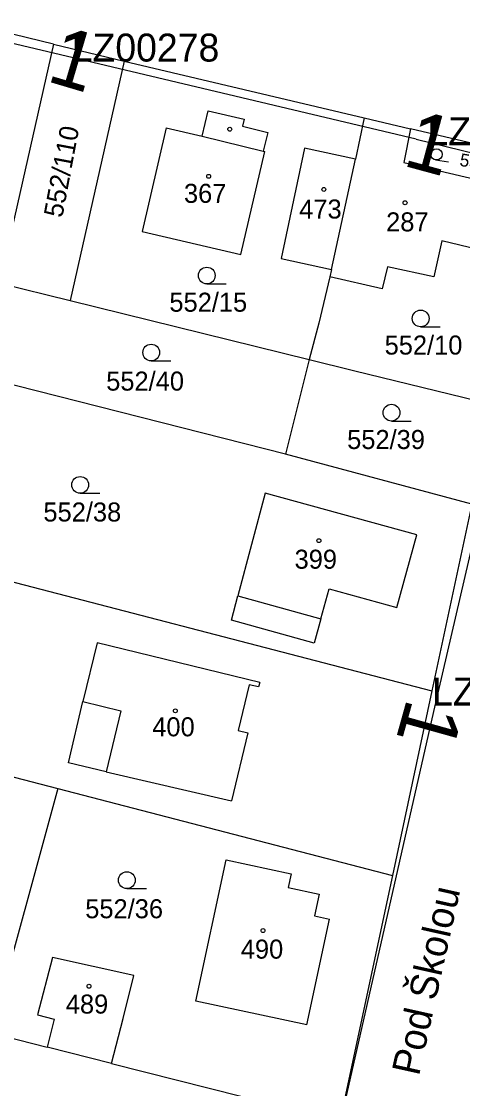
# Model space of a CAD drawing. Extents: x -738131 to -734179, y -1033447 to -1030078.
# Drawn here: x -735741.5 to -735702.1, y -1032052.3 to -1031956.9 of the extents above; entities that cross this region are included whole.
import ezdxf

# ---------------------------------------------------------------- set-up
doc = ezdxf.new("R2010")
doc.units = 0
for name, color, linetype in [('ftf_2010', 7, 'Continuous'), ('ftf_3010', 7, 'Continuous'), ('ftf_3010_ftf_3010_gtda_3015_gtda_3015_1', 7, 'Continuous'), ('ftf_nu', 7, 'Continuous'), ('Vrstva 1', 7, 'Continuous'), ('Vrstva 2', 7, 'Continuous'), ('Vrstva 3', 7, 'Continuous'), ('Vrstva 4', 7, 'Continuous'), ('Vrstva 5', 7, 'Continuous')]:
    doc.layers.add(name, color=color, linetype=linetype)

msp = doc.modelspace()

# ---------------------------------------------------------------- linework, layer by layer
at = {"layer": 'ftf_2010'}
for points in [[(-735738.005, -1031959.865), (-735766.976, -1031952.978)], [(-735706.213, -1031967.386), (-735738.005, -1031959.865)], [(-735706.213, -1031967.386), (-735694.255, -1031970.331), (-735693.952, -1031970.457), (-735694.586, -1031973.112), (-735694.474, -1031973.737)], [(-735698.776, -1031993.123), (-735704.656, -1032018.561)], [(-735704.656, -1032018.561), (-735713.631, -1032058.021)]]:
    msp.add_lwpolyline(points, dxfattribs=at)
at = {"layer": 'Vrstva 1'}
for points in [[(-735738.64, -1031958.92), (-735780.7, -1031948.62)], [(-735738.64, -1031958.92), (-735742.81, -1031977.4)], [(-735738.64, -1031958.92), (-735732.3, -1031960.42)], [(-735732.3, -1031960.42), (-735737.14, -1031981.83)], [(-735732.3, -1031960.42), (-735710.85, -1031965.49)], [(-735725.35, -1031967.12), (-735724.81, -1031964.85)], [(-735724.81, -1031964.85), (-735721.59, -1031965.61)], [(-735710.85, -1031965.49), (-735711.65, -1031969.18)], [(-735710.85, -1031965.49), (-735706.72, -1031966.47)], [(-735728.55, -1031966.37), (-735730.71, -1031975.65)], [(-735728.55, -1031966.37), (-735725.35, -1031967.12)], [(-735721.59, -1031965.61), (-735721.74, -1031966.25)], [(-735721.74, -1031966.25), (-735719.48, -1031966.79)], [(-735706.72, -1031966.47), (-735707.33, -1031969.47)], [(-735694.82, -1031969.28), (-735706.72, -1031966.47)], [(-735719.48, -1031966.79), (-735719.88, -1031968.46)], [(-735716.19, -1031968.2), (-735718.27, -1031978.06)], [(-735711.65, -1031969.18), (-735716.19, -1031968.2)], [(-735721.88, -1031977.71), (-735719.73, -1031968.49)], [(-735719.88, -1031968.46), (-735719.73, -1031968.49)], [(-735713.78, -1031979.04), (-735711.65, -1031969.18)], [(-735707.33, -1031969.47), (-735695.46, -1031972.26)], [(-735730.71, -1031975.65), (-735721.88, -1031977.71)], [(-735703.92, -1031976.49), (-735704.64, -1031979.7)], [(-735696.73, -1031978.21), (-735703.92, -1031976.49)], [(-735718.27, -1031978.06), (-735713.78, -1031979.04)], [(-735708.78, -1031978.81), (-735709.24, -1031980.76)], [(-735704.64, -1031979.7), (-735708.78, -1031978.81)], [(-735713.92, -1031979.69), (-735714.92, -1031983.85)], [(-735713.78, -1031979.04), (-735713.92, -1031979.69)], [(-735709.24, -1031980.76), (-735713.92, -1031979.69)], [(-735743.46, -1031980.28), (-735737.14, -1031981.83)], [(-735737.14, -1031981.83), (-735715.77, -1031987.08)], [(-735714.92, -1031983.85), (-735715.77, -1031987.08)], [(-735715.77, -1031987.08), (-735717.89, -1031995.55)], [(-735715.77, -1031987.08), (-735711.8, -1031988.06)], [(-735711.8, -1031988.06), (-735699.49, -1031991.09)], [(-735717.89, -1031995.55), (-735745.71, -1031988.48)], [(-735701.23, -1032000.01), (-735717.89, -1031995.55)], [(-735719.7, -1031999.03), (-735722.15, -1032008.2)], [(-735706.14, -1032002.77), (-735719.7, -1031999.03)], [(-735701.23, -1032000.01), (-735704.81, -1032016.7)], [(-735707.93, -1032009.27), (-735706.14, -1032002.77)], [(-735750.22, -1032004.92), (-735704.81, -1032016.7)], [(-735722.73, -1032010.38), (-735722.15, -1032008.2)], [(-735714.73, -1032010.26), (-735714, -1032007.6)], [(-735714, -1032007.6), (-735707.93, -1032009.27)], [(-735714.73, -1032010.26), (-735715.33, -1032012.44)], [(-735715.33, -1032012.44), (-735722.73, -1032010.38)], [(-735734.72, -1032012.42), (-735736, -1032017.67)], [(-735720.2, -1032015.95), (-735734.72, -1032012.42)], [(-735720.2, -1032015.95), (-735720.3, -1032016.36)], [(-735721.15, -1032016.16), (-735722.12, -1032020.25)], [(-735720.3, -1032016.36), (-735721.15, -1032016.16)], [(-735704.81, -1032016.7), (-735708.34, -1032033.2)], [(-735737.3, -1032023.15), (-735736, -1032017.67)], [(-735721.26, -1032020.45), (-735722.71, -1032026.55)], [(-735722.12, -1032020.25), (-735721.26, -1032020.45)], [(-735754.68, -1032021.16), (-735738.23, -1032025.43)], [(-735733.92, -1032023.94), (-735737.3, -1032023.15)], [(-735733.92, -1032023.94), (-735722.71, -1032026.55)], [(-735738.23, -1032025.43), (-735744.22, -1032047.27)], [(-735738.23, -1032025.43), (-735708.34, -1032033.2)], [(-735725.92, -1032044.43), (-735723.21, -1032031.81)], [(-735723.21, -1032031.81), (-735717.39, -1032033.06)], [(-735717.39, -1032033.06), (-735717.65, -1032034.29)], [(-735708.34, -1032033.2), (-735713.05, -1032055.16)], [(-735717.65, -1032034.29), (-735714.88, -1032034.88)], [(-735714.88, -1032034.88), (-735715.29, -1032036.8)], [(-735715.29, -1032036.8), (-735713.97, -1032037.1)], [(-735716, -1032046.56), (-735713.97, -1032037.1)], [(-735738.73, -1032040.53), (-735740.05, -1032045.66)], [(-735731.44, -1032042.16), (-735738.73, -1032040.53)], [(-735732.41, -1032045.99), (-735731.44, -1032042.16)], [(-735716, -1032046.56), (-735725.92, -1032044.43)], [(-735740.05, -1032045.66), (-735738.56, -1032046.05)], [(-735738.56, -1032046.05), (-735739.2, -1032048.54)], [(-735733.43, -1032050), (-735732.41, -1032045.99)], [(-735744.22, -1032047.27), (-735739.2, -1032048.54)], [(-735733.43, -1032050), (-735739.2, -1032048.54)], [(-735733.43, -1032050), (-735713.05, -1032055.16)]]:
    msp.add_lwpolyline(points, dxfattribs=at)
at = {"layer": 'Vrstva 3'}
for p, q in [((-735704.475, -1031969.251), (-735703.317, -1031969.435)), ((-735724.932, -1031980.34), (-735723.182, -1031980.34)), ((-735705.812, -1031984.17), (-735704.062, -1031984.17)), ((-735729.892, -1031987.22), (-735728.142, -1031987.22)), ((-735708.422, -1031992.59), (-735706.672, -1031992.59)), ((-735736.242, -1031999.05), (-735734.492, -1031999.05)), ((-735732.072, -1032034.38), (-735730.322, -1032034.38))]:
    msp.add_line(p, q, dxfattribs=at)
for centre, radius in [((-735704.396, -1031968.755), 0.503), ((-735724.932, -1031979.59), 0.75), ((-735705.812, -1031983.42), 0.75), ((-735729.892, -1031986.47), 0.75), ((-735708.422, -1031991.84), 0.75), ((-735736.242, -1031998.3), 0.75), ((-735732.072, -1032033.63), 0.75)]:
    msp.add_circle(centre, radius, dxfattribs=at)
at = {"layer": 'Vrstva 4'}
for points in [[(-735725.35, -1031967.12), (-735719.88, -1031968.46)], [(-735722.15, -1032008.2), (-735714.73, -1032010.26)], [(-735736, -1032017.67), (-735732.6, -1032018.5)], [(-735732.6, -1032018.5), (-735733.92, -1032023.94)]]:
    msp.add_lwpolyline(points, dxfattribs=at)
at = {"layer": 'Vrstva 5'}
for centre in [(-735722.877, -1031966.509), (-735724.757, -1031970.719), (-735714.467, -1031971.889), (-735707.207, -1031973.079), (-735714.907, -1032003.279), (-735727.737, -1032018.489), (-735719.907, -1032038.129), (-735735.457, -1032043.109)]:
    msp.add_circle(centre, 0.175, dxfattribs=at)

# ---------------------------------------------------------------- texts
at = {"layer": 'ftf_3010'}
for rotation, p in [(343.50549, (-735739.364, -1031962.174)), (344.8574, (-735707.517, -1031969.727)), (254.39105, (-735706.985, -1032017.238))]:
    msp.add_text('1', height=5.2, rotation=rotation, dxfattribs=at).set_placement(p)
at = {"layer": 'ftf_3010_ftf_3010_gtda_3015_gtda_3015_1'}
for s, p in [('LZ00278', (-735737.005, -1031960.461)), ('LZ00279', (-735705.213, -1031967.94)), ('LZ00287', (-735704.795, -1032018.02))]:
    msp.add_text(s, height=2.5, dxfattribs=at).set_placement(p)
at = {"layer": 'ftf_nu'}
msp.add_text('Pod Školou', height=2.5, rotation=77.46081, dxfattribs=at).set_placement((-735705.968, -1032051.194))
at = {"layer": 'Vrstva 2'}
for s, height, rotation, p in [('552/110', 1.7, 79.30348, (-735737.846, -1031974.476)), ('552/109', 1.14, 350.70667, (-735702.38, -1031969.775))]:
    msp.add_text(s, height=height, rotation=rotation, dxfattribs=at).set_placement(p)
for s, p in [('367', (-735726.966, -1031973.09)), ('473', (-735716.666, -1031974.49)), ('287', (-735708.897, -1031975.64)), ('552/15', (-735728.27, -1031982.82)), ('552/10', (-735709.032, -1031986.65)), ('552/40', (-735733.918, -1031989.87)), ('552/39', (-735712.382, -1031995.09)), ('552/38', (-735739.53, -1032001.57)), ('399', (-735717.081, -1032005.79)), ('400', (-735729.802, -1032020.77)), ('552/36', (-735735.792, -1032037.03)), ('490', (-735721.888, -1032040.64)), ('489', (-735737.528, -1032045.55))]:
    msp.add_text(s, height=1.7, dxfattribs=at).set_placement(p)

doc.saveas('drawing.dxf')
